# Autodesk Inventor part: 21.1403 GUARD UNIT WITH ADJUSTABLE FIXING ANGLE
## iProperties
Created: 2007-01
Part Number: 21.1403 GUARD UNIT WITH ADJUSTABLE FIXING ANGLE
Material: Aluminum-6061
Document SubType Name: Modeling
Designer: Andy Moles
Density: 2.71 g/cm^3
Author: Andy Moles
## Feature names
1. Base1
